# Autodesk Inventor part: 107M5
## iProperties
Shininess: 70.0
Length Units: 11269
Angle Units: 11279
Time Units: 11290
Mass Units: 11284
Length Display Precision: 3
Angle Display Precision: 2
Compacted: True
Company: Pneumax S.p.A.
Part Number: 107M5
Document SubType Name: Modeling
Catalog Web Link: www.pneumaxspa.com
Created: 2003-04
Designer: A. Maffi
Description: TAPPO MASCHIO M5 CIL.
Density: 0.0
Volumn: 0.0
Area: 0.0
PropertySet Name: Model Information
Control State: 0
Master: False
Checked Out: False
Author: A. Maffi
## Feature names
1. Rivoluzione1 [Revolution]
2. Estrusione1 [Extrusion]
